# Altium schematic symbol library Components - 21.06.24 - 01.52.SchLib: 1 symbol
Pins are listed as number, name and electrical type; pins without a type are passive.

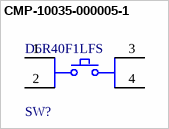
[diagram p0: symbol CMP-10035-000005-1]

## CMP-10035-000005-1
designator SW?, comment D6R40F1LFS
SWITCH PUSH SPST-NO 0.1A 32V; Switch Function: Off-Mom; Number of Poles: 1; Insulation Resistance: 100GR; Contact Resistance: 100mR; Actuator Length: 7mm; Row Spacing: 5mm; Max Current Rating: 100mA; Electrical Life: 250000Cycles; Number of Terminals/Pins: 4; Operating Force: 1.3N; Actuator Type: Round, Button; Throw Configuration: SPST; Actuator Color: Red; Illumination Type: Illuminated; Power Rating: 3W; Outside Diameter: 12mm; Voltage Rating (AC): 100V
footprint FP-D6R40F1LFS-MFG
pins: 1, 2, 3, 4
